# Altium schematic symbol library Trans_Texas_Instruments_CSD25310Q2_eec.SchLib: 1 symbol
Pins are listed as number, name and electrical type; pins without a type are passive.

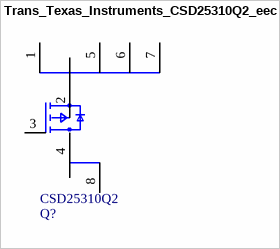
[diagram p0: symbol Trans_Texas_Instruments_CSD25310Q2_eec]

## Trans_Texas_Instruments_CSD25310Q2_eec
designator Q?  Part Number: CSD25310Q2
TRANS MOSFET P-CH 20V 48A 6SON; Manufacturer: Texas Instruments; Mfg Package Ident: DQK
footprint Texas_Instruments_DQK_0
pins: 1 S, 2 S, 3 G, 4 D, 5 S, 6 S, 7 S PAD, 8 D PAD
